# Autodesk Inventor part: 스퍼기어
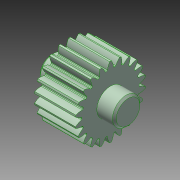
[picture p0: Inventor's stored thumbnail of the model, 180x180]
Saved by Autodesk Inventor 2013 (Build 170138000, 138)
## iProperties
Created: 2024-02
Part Number: 스퍼기어
Material: 강철, 탄소
Document SubType Name: Modeling
Designer: mdu-01
Density: 1 g/cm^3
Author: mdu-01
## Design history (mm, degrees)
sketch "스케치1"
  geometry: L1 (-19.5, 0)-(19.5, 0); L2 (19.5, 0)-(19.5, 6); L3 (18.5, 7)-(10.5, 7); L4 (10.5, 7)-(10.5, 14.625); L5 (10.5, 14.625)-(-10.5, 14.625); L6 (-10.5, 14.625)-(-10.5, 7); L7 (-10.5, 7)-(-18.5, 7); L8 (-19.5, 6)-(-19.5, 0); L9 (-18.5, 7)-(-19.5, 6); L10 (19.5, 6)-(18.5, 7); L11 (-10.5, 16.5)-(10.5, 16.5); 4 further points
  constraints: 22 end point, 6 parallel, 6 point on line, 2 collinear, 2 perpendicular, 1 coincident, 1 horizontal, 1 midpoint
  dimensions: "d0" = 1 distance of L7.end point (-19.5, 7); "d1" = 1 distance of L8.start point (-19.5, 7) (= d0); "d2" = 1 distance of L2.end point (19.5, 7) (= d0); "d3" = 1 distance of L3.start point (19.5, 7) (= d2); "d4" = 9 distance between parallel lines of L8 L6; "d5" = 21 distance between parallel lines of L4 L6; "d6" = 33 diameter of L11 L1; "d7" = 1.875 distance between parallel lines of L5 L11; "d8" = 14 diameter of L7 L1
revolve "회전1" sketch "스케치1" stored, may be unused: angle "d9" = 90 deg
sketch "스케치2" dims "d10" = 33
  geometry: L1 (0, 0)-(18, 0); A1 r 18 centre (0, 0) between (17.995, -0.428) and (17.995, 0.428); A2 r 7.045 centre (14.16, 5.482) between (14.542, -1.553) and (17.995, -0.428); A3 r 7.045 centre (14.16, -5.482) between (17.995, 0.428) and (14.542, 1.553); A4 r 14.625 centre (0, 0) between (14.542, -1.553) and (14.542, 1.553); 4 further points
  constraints: 10 point on circle, 4 centre point, 3 symmetric about line, 2 coincident, 2 end point, 1 horizontal, 8 other
  dimensions: "d11" = 1.5 dimension on A1; "d12" = 1.1775 distance from line of point (16.458, -1.178) L1; "d13" = 0.75 vertical distance of A1.start point (16.458, -1.178); "d14" = 0.375 vertical distance of A2.start point (16.458, -1.178)
extrude "돌출1" join sketch "스케치2" stored distance "d15" = 10; taper "d16" = 0 deg
fillet "모깎기1" dims "d17" = 0.375
node "솔리드1"
pattern_circular "원형 패턴1" dims angle "d19" = 360 deg
